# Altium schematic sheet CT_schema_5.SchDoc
size 372 x 243 mm
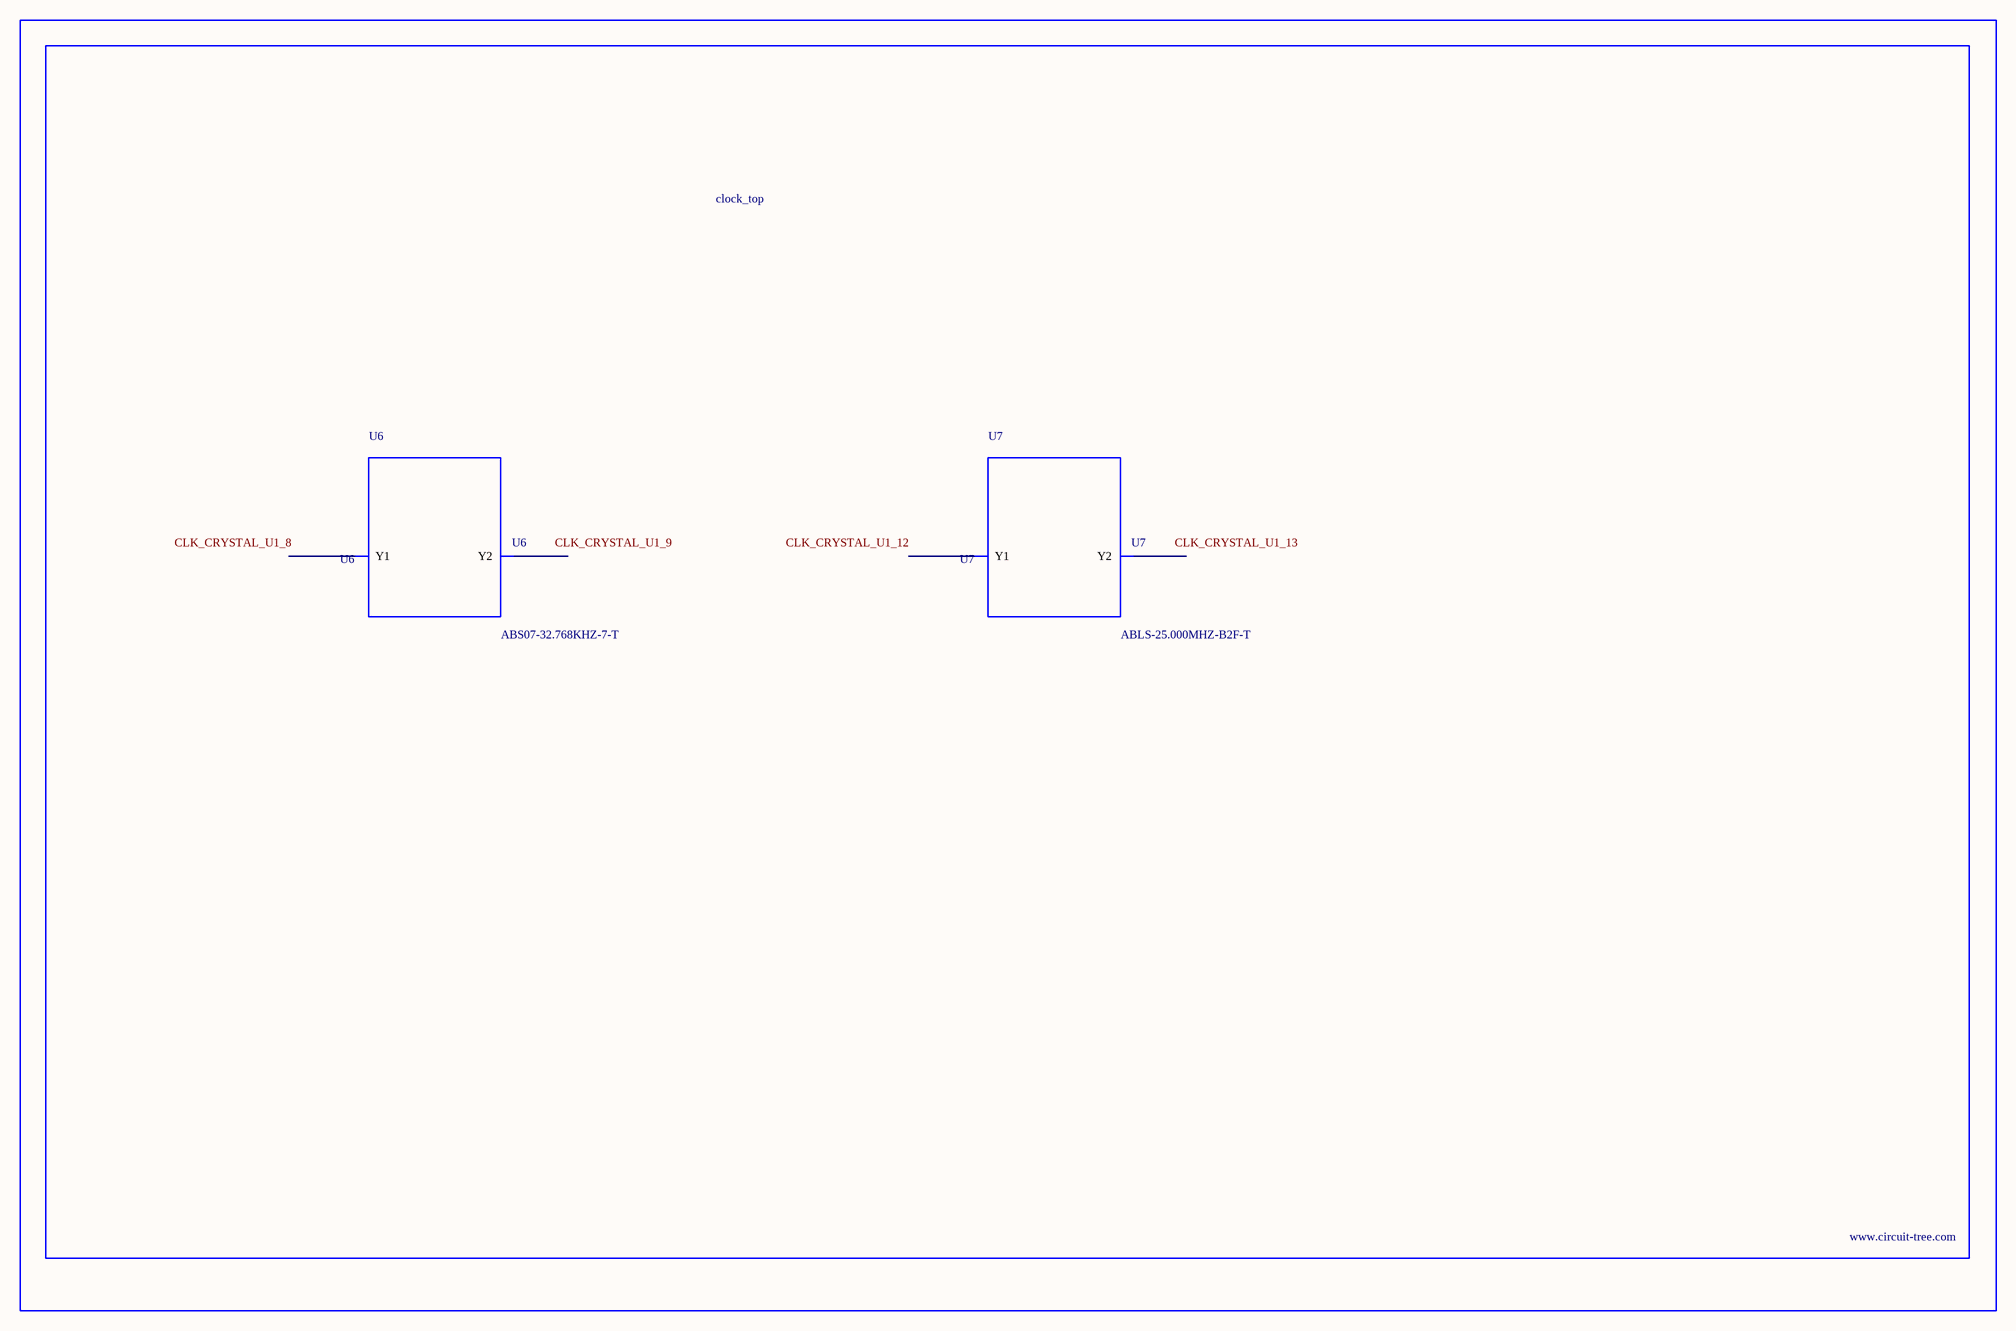
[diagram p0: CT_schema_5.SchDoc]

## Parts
BORDER4  (no value)
U6  ABS07-32.768KHZ-7-T  [ABS07-32.768KHZ-7-T]
U7  ABLS-25.000MHZ-B2F-T  [ABLS-25.000MHZ-B2F-T]

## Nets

Not connected (* = marked no-connect by the designer): U6 1(Y1) 2(Y2); U7 1(Y1) 2(Y2)

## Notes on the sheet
- Labels drawn without touching a wire or pin: CLK_CRYSTAL_U1_8, CLK_CRYSTAL_U1_9, CLK_CRYSTAL_U1_12, CLK_CRYSTAL_U1_13

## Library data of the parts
BORDER4 = BORDER_PAGE4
